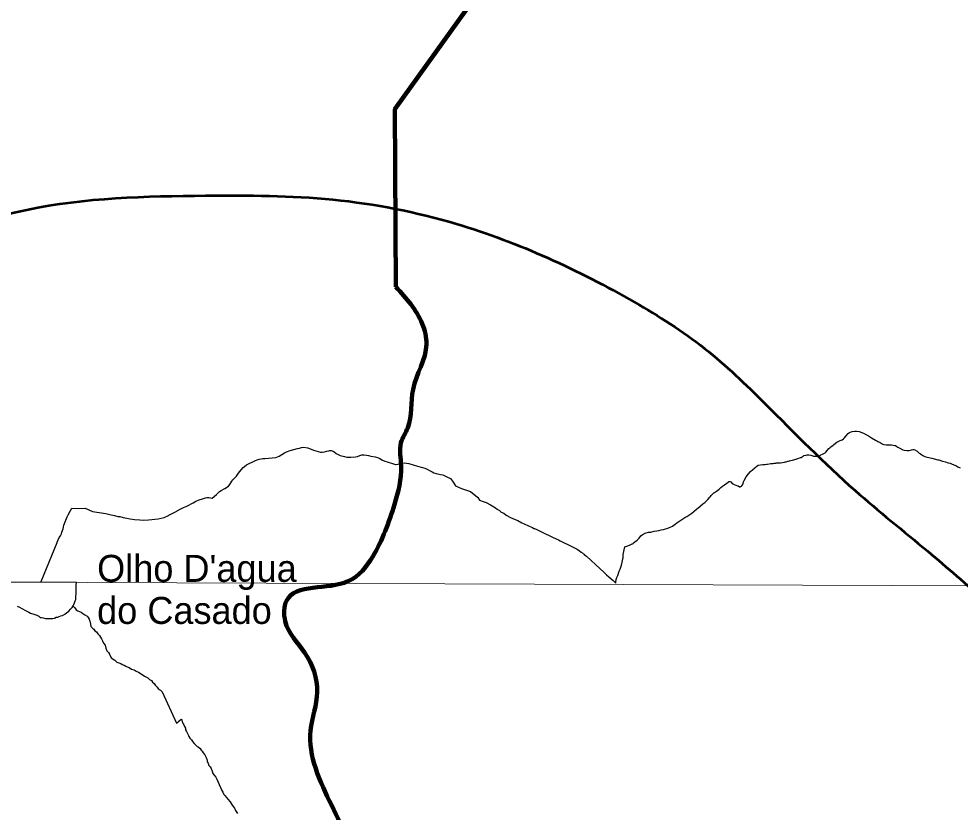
# Model space of a CAD drawing. Extents: x -1643653 to 4543381, y 1624270 to 13878484.
# Drawn here: x 627893 to 645322, y 8945383 to 8960077 of the extents above; entities that cross this region are included whole.
import ezdxf

# ---------------------------------------------------------------- set-up
doc = ezdxf.new("R2010")
doc.units = 0
doc.header["$LTSCALE"] = 200
for name, color, linetype, lineweight in [('1', 7, 'Continuous', 13), ('12', 7, 'Continuous', 25), ('21', 7, 'Continuous', 25), ('23', 7, 'Continuous', 13), ('28', 7, 'Continuous', 53), ('60', 7, 'Continuous', 13), ('9', 7, 'Continuous', 90)]:
    doc.layers.add(name, color=color, linetype=linetype, lineweight=lineweight)
doc.layers.add('41', color=7, linetype='Continuous')

msp = doc.modelspace()

# ---------------------------------------------------------------- linework, layer by layer
at = {"layer": '1'}
msp.add_line((565315.3, 8949866.8), (791497.7, 8949052.2), dxfattribs=at)
at = {"layer": '12'}
for points in [[(642470.5, 8951998.4), (642488.5, 8952001.9), (642522.6, 8951999.2), (642556.7, 8951992.9), (642592.3, 8951983), (642609.4, 8951976.9), (642626.5, 8951976.6), (642642.7, 8951974.7), (642676.8, 8951977.7), (642721, 8951987.2), (642724.8, 8951990.9), (642735.1, 8951994.5), (642743.5, 8952000), (642776.2, 8952012.3), (642776.2, 8952012.3), (642820.9, 8952041.1), (642834.6, 8952053), (642890.7, 8952119.2), (642906.7, 8952133.2), (642928.9, 8952148.8), (642967.9, 8952182.8), (642985, 8952193.5), (643037.1, 8952235.1), (643053.7, 8952245), (643102.2, 8952265.8), (643135, 8952282.2), (643159.6, 8952300.8), (643178.3, 8952317.8), (643202.9, 8952349.8), (643246, 8952395.7), (643257.2, 8952401.9), (643271.1, 8952413.3), (643302.7, 8952429.5), (643320.6, 8952432.8), (643369.3, 8952438.9), (643405.8, 8952441), (643454.6, 8952432.6), (643499.9, 8952415)], [(643499.9, 8952415), (643545.2, 8952397.3), (643559.2, 8952390.7), (643566.2, 8952384), (643622.9, 8952353.1), (643662.1, 8952326.2), (643681.9, 8952316.1), (643757.2, 8952271.2), (643777.1, 8952261.1), (643797.8, 8952247.5), (643838.2, 8952227.2), (643875.4, 8952204.5), (643892.2, 8952196.2), (643909.7, 8952190.3), (643950.5, 8952184.5), (644032, 8952186.5), (644053.2, 8952185.5), (644110.7, 8952177), (644118, 8952173), (644124.4, 8952171.9), (644149.9, 8952156.7), (644169.2, 8952143), (644206.8, 8952123.1), (644263.5, 8952096.7), (644288, 8952088.8), (644341, 8952079.2), (644360.9, 8952079), (644380.1, 8952081.2), (644401.4, 8952086.5), (644422.7, 8952094.8), (644444, 8952099.1), (644465.3, 8952100.1), (644485.8, 8952097), (644525.6, 8952067.7), (644562.3, 8952035.3), (644585, 8952018.8), (644610.2, 8952003.3), (644630.2, 8951989.1), (644666.2, 8951972.1), (644686.9, 8951965), (644764.8, 8951944.4), (644796.3, 8951937.1)], [(631977.1, 8951685.3), (632043.8, 8951765.5), (632068.1, 8951787.6), (632108.7, 8951813.7), (632273.3, 8951897.1), (632308.2, 8951910.2), (632340.4, 8951920.2), (632377.3, 8951927.3), (632410.5, 8951931.4), (632445.5, 8951933.4), (632583, 8951943.7), (632651.1, 8951951.8), (632683.3, 8951961.8), (632714.5, 8951977.9), (632813.6, 8952039.2), (632846.3, 8952056.3), (632917.7, 8952084.4), (633052.1, 8952118.7), (633089.1, 8952126.8), (633126.8, 8952136.8), (633162.7, 8952142.2)], [(633162.7, 8952142.2), (633241, 8952131), (633351.4, 8952085.1), (633389.4, 8952073.2), (633476, 8952053.2), (633512.3, 8952049.3), (633554.8, 8952055.4), (633594.5, 8952068.5), (633634.9, 8952078.5), (633648.8, 8952084.6), (633676.3, 8952083.6), (633727.4, 8952060.7), (633770.1, 8952027.7), (633804.1, 8952004.7), (633842.6, 8951989.7), (633923.6, 8951967.8), (633963.1, 8951960.9), (634004.5, 8951957.9), (634043, 8951958), (634125.1, 8951962.1), (634165.6, 8951972.2), (634207, 8951990.3), (634246.6, 8951999.4), (634288, 8952002.5), (634328.5, 8951997.5), (634368.9, 8951987.6), (634409.5, 8951974.6), (634490.4, 8951962.7), (634530.8, 8951952.8), (634579.8, 8951930.8), (634627.9, 8951901.8), (634668.1, 8951883.9), (634709.8, 8951868.9), (634829.3, 8951833.1), (634866.1, 8951824.1)], [(640395.6, 8950959.1), (640439.6, 8950994.5), (640445, 8950997), (640447, 8951000.5), (640457.8, 8951007.8), (640555.3, 8951093.5), (640594.1, 8951120.7), (640626.7, 8951148.9), (640649.6, 8951173.9), (640686.4, 8951218.1), (640699.1, 8951231), (640711, 8951247), (640763.7, 8951297.4), (640775.4, 8951302.8), (640813.7, 8951328.4), (640837.7, 8951348), (640857.9, 8951367.2), (640891.5, 8951395.5), (640923.9, 8951418.5), (640957.6, 8951446.5), (641002, 8951475.6), (641024.2, 8951496.1), (641040.4, 8951506.2), (641048.4, 8951506.8), (641063.8, 8951505.7), (641076.1, 8951500.8), (641103, 8951472.9), (641113.2, 8951465), (641125.4, 8951459), (641140.6, 8951455), (641169.7, 8951440.6), (641200.2, 8951430.5), (641213.3, 8951424.4), (641238.7, 8951409.4), (641250.3, 8951409.1), (641257, 8951415.1), (641263.6, 8951416.6), (641271.5, 8951423.5), (641278.8, 8951426.2), (641300.2, 8951451.3), (641301.2, 8951463.4), (641305.1, 8951471.8), (641310.1, 8951499.8), (641314, 8951513.2), (641320.4, 8951528.1), (641359.3, 8951592.4), (641405.6, 8951650.4), (641442.9, 8951693.2), (641484.3, 8951731.3), (641515.2, 8951757.2), (641526.5, 8951768.3), (641559, 8951794.4), (641579.3, 8951807.2), (641667.6, 8951821), (641713.1, 8951823.5), (641738.9, 8951828.1), (641757.8, 8951829.8), (641786.9, 8951836), (641814.4, 8951840), (641860.7, 8951842.5), (641877.2, 8951846.8), (641891.3, 8951848.7), (641906.2, 8951849), (641921.9, 8951853), (641936.1, 8951853.2), (641951.8, 8951855.2), (641995, 8951856.3), (642070.3, 8951868.1), (642085.2, 8951872.2), (642100.9, 8951874.6), (642130, 8951881.9), (642144.9, 8951887.1), (642160.5, 8951889.6), (642189.7, 8951897.8), (642218.7, 8951904.1), (642234.4, 8951909.5), (642263.5, 8951916.8), (642278.1, 8951923.3), (642336.6, 8951938.4), (642365, 8951949.3), (642376.5, 8951955.1), (642413.4, 8951978.7), (642427.4, 8951986.2), (642470.5, 8951998.4)], [(634866.1, 8951824.1), (634873.4, 8951824.1), (634910.2, 8951826.2), (634950.7, 8951837.2), (634989.1, 8951847.3), (635028.1, 8951852.4), (635071.3, 8951849.5), (635114.6, 8951840.5), (635272.6, 8951793.7), (635367.2, 8951768.8), (635408.9, 8951751.8), (635451.4, 8951736.9), (635498.6, 8951712.9), (635544.2, 8951684), (635579.4, 8951666), (635619.9, 8951654), (635700.8, 8951640.1), (635740.5, 8951628.2), (635792.4, 8951609.2), (635828.7, 8951590.2), (635872.5, 8951570.3), (635883.6, 8951562.3), (635922.4, 8951513.3), (635950.1, 8951475.3), (635979.6, 8951429.2), (636087.1, 8951379.3), (636253.1, 8951319.5), (636386.5, 8951215.6), (636391.7, 8951209.6), (636419.7, 8951164.5), (636421.7, 8951160.5), (636421.7, 8951160.5), (636421.7, 8951160.5)], [(644796.3, 8951937.1), (644909.5, 8951910.6), (644920.9, 8951908.3), (644925, 8951908), (644979.4, 8951891), (644998, 8951886), (645049.9, 8951868.9), (645083.2, 8951861.5), (645101.9, 8951853.7), (645139.4, 8951844.3), (645159.2, 8951837.9), (645204.5, 8951819), (645240.2, 8951802.2), (645277.4, 8951781.6), (645324.7, 8951759)], [(628309.2, 8949653.4), (628599.7, 8950377.9), (628601.3, 8950384.9), (628641.4, 8950470.1), (628663, 8950503.2), (628681.3, 8950538.3), (628691.8, 8950567.4), (628700.4, 8950599.4), (628711, 8950631.5), (628727.3, 8950696.6), (628774.6, 8950822.9), (628788.9, 8950856), (628806.9, 8950888.1), (628840.8, 8950956.2), (628872.2, 8951013.3), (628996.9, 8951009.5), (629121.2, 8951016.8), (629253.8, 8950950.8), (629505.9, 8950912.2), (629601.8, 8950889.3), (629665.7, 8950879.4), (629728.8, 8950861.5), (629762.5, 8950857.5), (629825.6, 8950843.6), (629857.5, 8950834.6), (629889.5, 8950829.7), (629956.5, 8950815.8), (630035.3, 8950806.9), (630130.2, 8950799), (630192.3, 8950791.1), (630294.1, 8950795.2), (630475.3, 8950814.6), (630582.1, 8950842.8), (630610.8, 8950852.8), (630639.6, 8950867.9), (630696.5, 8950894.1), (630755.1, 8950927.2), (630784, 8950940.3), (630880.8, 8950995.5), (630942.3, 8951026.6), (631001.9, 8951051.8), (631119.9, 8951113.1), (631172.4, 8951142.2), (631232.1, 8951169.3), (631292.6, 8951189.5), (631346.6, 8951202.6), (631380.4, 8951208.6), (631413.7, 8951209.7), (631469.4, 8951200.8), (631474.6, 8951200.8), (631553, 8951268), (631581, 8951297.1), (631608.2, 8951320.2), (631637.5, 8951342.2), (631707.2, 8951377.4), (631776.4, 8951422.6), (631796.8, 8951451.7), (631836.1, 8951514.8), (631854.5, 8951538.9), (631890.1, 8951573), (631921.4, 8951606.1), (631949.1, 8951643.2), (631977.1, 8951685.3), (631977.1, 8951685.3)], [(636421.7, 8951160.5), (636492.6, 8951137.6), (636543.8, 8951117.6), (636626.9, 8951075.7), (636719.5, 8951017.8), (636751.5, 8950995.8), (636795.3, 8950967.8), (636826.1, 8950942.8), (636870.7, 8950918.8), (636915.4, 8950886.9), (636996.5, 8950842.9), (637085.1, 8950803), (637131.6, 8950784.1), (637204.7, 8950745.1)], [(639116.2, 8950297.4), (639149.8, 8950312.8), (639201.4, 8950330), (639225.8, 8950341.2), (639251, 8950352), (639254.3, 8950354.5), (639265.5, 8950361.8), (639275.1, 8950369.6), (639340.1, 8950423.9), (639377.5, 8950461.2), (639409.6, 8950499.5), (639433.2, 8950522.9), (639488.6, 8950549.3), (639509.1, 8950557.4), (639550.9, 8950566.9), (639593.5, 8950572.4), (639658.3, 8950586.3), (639703.6, 8950591.1), (639744.3, 8950599.4), (639786.9, 8950612), (639828.7, 8950619.4), (639850, 8950624.7), (639890, 8950637.6), (639937.9, 8950655.7), (639994.2, 8950681.9), (640048.1, 8950716.4), (640078.5, 8950742.4), (640115.7, 8950767), (640133.5, 8950781.2), (640151.5, 8950793.1), (640167.6, 8950806.8), (640226.6, 8950841.8), (640263.4, 8950861.3), (640263.4, 8950861.3), (640280.4, 8950873), (640297.6, 8950886.7), (640316.3, 8950898), (640351.7, 8950923.7), (640395.6, 8950959.1)], [(637204.7, 8950745.1), (637236.4, 8950731.9), (637342.1, 8950681.2), (637402.5, 8950654.2), (637429.5, 8950639.7), (637442.2, 8950635.2), (637481.3, 8950617.9), (637571.5, 8950575), (637632.7, 8950543.3), (637724.2, 8950501.8), (637761.9, 8950483), (637855.8, 8950440.2), (637882.2, 8950429.6), (637917.4, 8950409.5), (638134, 8950306.5), (638157.9, 8950291.9), (638228.5, 8950253.9), (638272.8, 8950224.6), (638304.2, 8950197.7), (638316.9, 8950191.8), (638323.7, 8950184.3), (638335.4, 8950179.9), (638341.5, 8950174.2), (638346.7, 8950171.6), (638352.3, 8950164.8), (638359.3, 8950163), (638363.3, 8950157.6), (638382.1, 8950140), (638404.6, 8950123.8), (638657.4, 8949892.2), (638716.1, 8949835.5), (638775.8, 8949782.1), (638818.1, 8949741), (638898.3, 8949671.3), (638932.1, 8949635.9), (638944.8, 8949626.3), (638949.6, 8949652.2), (638952.9, 8949690.6), (638957.5, 8949711.3), (638963.7, 8949729.7), (638981, 8949766.6), (639010.6, 8949844.8), (639027.5, 8949883.2), (639052, 8949959.9), (639066.5, 8950015.8), (639075.2, 8950073.3), (639081, 8950095.8), (639085, 8950131.7), (639085.5, 8950153.3), (639116.2, 8950297.4)], [(628906.4, 8949193.4), (628921.3, 8949173.3), (628943.6, 8949150.6), (628956, 8949130.5), (628983.3, 8949110.3), (629015.8, 8949102.6), (629048.2, 8949084.8), (629080.5, 8949064.6), (629117.8, 8949036.8), (629155.2, 8949016.5), (629177.5, 8948991.3), (629197.3, 8948958.7), (629204.5, 8948921.1), (629221.6, 8948865.9), (629226.2, 8948820.8), (629261, 8948788), (629283.4, 8948770.3), (629298.2, 8948742.7), (629330.6, 8948725), (629352.8, 8948687.2), (629385, 8948654.5), (629404.8, 8948624.3), (629422.1, 8948591.7), (629441.8, 8948556.5), (629459, 8948516.3), (629488.7, 8948473.6), (629503.3, 8948423.4), (629522.9, 8948370.7), (629552.7, 8948342.9), (629572.5, 8948307.8), (629604.5, 8948240), (629669.2, 8948197)], [(629669.2, 8948197), (629708.9, 8948159.2), (629743.8, 8948146.4), (629783.8, 8948136.1), (629808.6, 8948118.4), (629841.1, 8948105.7), (629875.9, 8948088), (629898.4, 8948077.8), (629935.8, 8948062.5), (629978.1, 8948034.7), (630025.5, 8948021.9), (630067.8, 8947994.1), (630107.7, 8947976.3), (630157.5, 8947945.9), (630219.7, 8947905.4), (630282, 8947872.5), (630311.8, 8947839.7), (630351.7, 8947824.4), (630368.9, 8947791.8), (630401.2, 8947769), (630421, 8947728.8), (630455.7, 8947696.1), (630480.5, 8947660.8), (630515.3, 8947640.6), (630547.6, 8947610.3), (630810.8, 8947030.3)], [(630810.8, 8947030.3), (630898.9, 8947107.3), (630908.8, 8947087.2), (630916.1, 8947062.1), (630926, 8947042), (630938.3, 8947019.4), (630948.1, 8946999.3), (630960.4, 8946969.2), (630977.7, 8946941.6), (630980, 8946909), (630999.7, 8946878.8), (631017, 8946838.7), (631034.2, 8946803.5), (631041.5, 8946783.4), (631056.3, 8946755.8), (631091.1, 8946723), (631108.4, 8946692.8), (631140.6, 8946657.6), (631160.5, 8946637.4), (631192.7, 8946599.7), (631215.2, 8946594.5), (631247.5, 8946564.2), (631269.7, 8946534.1), (631289.6, 8946511.4), (631306.9, 8946483.7), (631339.1, 8946443.5), (631358.7, 8946395.8), (631378.4, 8946345.6), (631380.6, 8946313), (631395.5, 8946292.9), (631412.6, 8946250.2), (631432.4, 8946222.5), (631452.2, 8946189.9), (631469.4, 8946144.7), (631486.6, 8946102), (631508.8, 8946069.3), (631541, 8946029.1), (631560.8, 8945993.9), (631627.1, 8945838.2)], [(631627.1, 8945838.2), (631649.2, 8945785.5), (631669, 8945752.8), (631686.2, 8945710.1), (631706, 8945690), (631740.8, 8945654.7), (631765.6, 8945627), (631805.2, 8945576.7), (631822.5, 8945544), (631842.2, 8945511.3), (631884.3, 8945456), (631906.5, 8945413.3), (631938.6, 8945360.5)]]:
    msp.add_lwpolyline(points, dxfattribs=at)
at = {"layer": '21'}
msp.add_lwpolyline([(627859, 8949198.2), (627903.8, 8949177.9), (627948.7, 8949152.7), (628014.1, 8949120.8), (628075.7, 8949086.9), (628110.6, 8949066.7), (628173, 8949048.9), (628225.4, 8949033.6), (628265.2, 8949010.9), (628287.6, 8948988.2), (628315.1, 8948988.1), (628342.5, 8948985.4), (628384.9, 8948970.2), (628409.9, 8948970.1), (628442.4, 8948969.9), (628474.9, 8948969.7), (628499.9, 8948969.6), (628525, 8948972), (628555, 8948976.8), (628582.6, 8948994.2), (628612.6, 8948994), (628640.2, 8949006.4), (628670.3, 8949021.2), (628702.8, 8949023.6), (628745.5, 8949053.4), (628778.1, 8949073.2), (628818.4, 8949105.5), (628848.6, 8949140.4), (628878.8, 8949175.3), (628896.5, 8949205.2), (628909.2, 8949232.7), (628924.4, 8949257.6), (628937.2, 8949297.6), (628949.8, 8949325), (628950, 8949352.6), (628950.3, 8949387.6), (628952.9, 8949412.6), (628953.3, 8949462.7), (628953.4, 8949482.7), (628953.7, 8949520.2), (628953.8, 8949540.2), (628954, 8949562.7), (628954.2, 8949595.3), (628960.2, 8949636.4), (627600.1, 8949642.9)], dxfattribs=at)
at = {"layer": '23'}
msp.add_spline([(618257.6, 8953925.9), (619183.7, 8953970.3), (620725.9, 8954192.9), (622371.6, 8954682.1), (623953.8, 8955209.7), (626185.5, 8955995.2), (628043.5, 8956541.4), (631351.2, 8956802.4), (633709.5, 8956728.8), (635993.8, 8956280.5), (637686.3, 8955648.2), (639291.4, 8954828.8), (640588.9, 8953973.3), (641709, 8952948.6), (643376.9, 8951340.4), (644721.9, 8950215.5), (645793.1, 8949290.9)], degree=3, dxfattribs=at)
msp.add_spline([(618257.6, 8953925.9), (619183.7, 8953970.3), (620725.9, 8954192.9), (622371.6, 8954682.1), (623953.8, 8955209.7), (626185.5, 8955995.2), (628043.5, 8956541.4), (631351.2, 8956802.4), (633709.5, 8956728.8), (635993.8, 8956280.5), (637686.3, 8955648.2), (639291.4, 8954828.8), (640588.9, 8953973.3), (641709, 8952948.6), (643376.9, 8951340.4), (644721.9, 8950215.5), (645793.1, 8949290.9)], degree=3, dxfattribs=at)
at = {"layer": '28'}
msp.add_spline([(618257.6, 8953925.9), (619183.7, 8953970.3), (620725.9, 8954192.9), (622371.6, 8954682.1), (623953.8, 8955209.7), (626185.5, 8955995.2), (628043.5, 8956541.4), (631351.2, 8956802.4), (633709.5, 8956728.8), (635993.8, 8956280.5), (637686.3, 8955648.2), (639291.4, 8954828.8), (640588.9, 8953973.3), (641709, 8952948.6), (643376.9, 8951340.4), (644721.9, 8950215.5), (645793.1, 8949290.9)], degree=3, dxfattribs=at)
at = {"layer": '60', "lineweight": 25}
msp.add_spline([(814781, 9009175.5), (814787.2, 9009173.4), (814796.9, 9009173.4), (814799.4, 9009172.4), (814805.1, 9009174.5), (814805.6, 9009176.5), (814811.7, 9009179.5), (814811.7, 9009179.5), (814801.5, 9009181), (814790.7, 9009181.5), (814784.1, 9009183.1), (814777.4, 9009185.1), (814778.4, 9009175.5)], degree=3, dxfattribs=at)
at = {"layer": '9'}
msp.add_lwpolyline([(637260.6, 8972975.8), (637076.8, 8961505.7), (634855.7, 8958401.3), (634875.3, 8955110.3)], dxfattribs=at)
for points in [[(637260.6, 8972975.8), (641524.5, 8971056.2), (652526.1, 8965412.7), (653164.3, 8965062.8), (670790.5, 8953770.1), (686194, 8943929.9), (696283.3, 8937647.1)], [(630387.4, 8939797.8), (630434.2, 8940142.1), (630686.5, 8940523.6), (631192.1, 8941084.2), (631927.5, 8941519.8), (632256.1, 8941901.8), (632534.2, 8942207.6), (633141.9, 8942718.3), (633623.2, 8943101.4), (634002.9, 8943433.2), (634103.5, 8943636.5), (634126.4, 8944067), (633968.9, 8944876), (633685.2, 8945506.9), (633295.3, 8946896.6), (633418.3, 8947606.3), (633184.9, 8948338.8), (632825.2, 8948918.6), (632848.4, 8949298.5), (633991.4, 8949661), (634446.8, 8950119.9), (634848.2, 8951084.8), (634971.3, 8951794.5), (634968.7, 8952224.9), (635094.3, 8952504.3), (635191.9, 8953213.8), (635441.4, 8954051.1), (635362.8, 8954430.2), (634875.3, 8955110.3)]]:
    msp.add_spline(points, degree=3, dxfattribs=at)

# ---------------------------------------------------------------- texts
at = {"layer": '41'}
for s, p in [("Olho D'agua", (629342.2, 8949648.8)), ('do Casado', (629342.2, 8948869.8))]:
    msp.add_text(s, height=500, dxfattribs=at).set_placement(p)

doc.saveas('drawing.dxf')
